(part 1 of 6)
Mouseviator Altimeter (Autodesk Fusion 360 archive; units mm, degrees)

design "Mouseviator Altimeter" references "ULN2003 Stepper Driver v18", "28BYJ-48", "10 turn potentiometer", "Bezel VSI & ALT MS33549B"
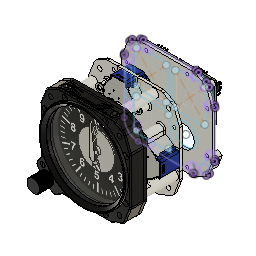
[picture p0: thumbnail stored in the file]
parameter "MagnetDiameter" = 3
parameter "ShaftRotatyToll" = 0.3
parameter "ShaftThickness" = 1
parameter "GluePressFitToll" = 0.1
parameter "squareShaft" = 3.5
parameter "StepperTightness" = 0.3
parameter "DShaftToll" = 0.2
canvas "Canvas1"
canvas "Canvas1" bodies "Faceplate"
external_derived "Front Face" bodies "ALT VSI Bezel", "Seal", "Body1", "Body2", "Top LED Holder"
derived_instance "DerivedInstance1"
derived_instance "DerivedInstance1"
derived_instance "DerivedInstance2"
derived_instance "DerivedInstance3"
derived_instance "DerivedInstance4"
derived_instance "DerivedInstance1"
derived_instance "DerivedInstance2"
extrude "Extrude3" cut of existing geometry blind -0.15
extrude "Extrude4" cut of existing geometry blind -0.15
offset_faces "OffsetFaces1" distance -0.15
extrude "Extrude2" add of existing geometry blind 1.5
extrude "Extrude1" add of existing geometry to an object
sketch "Sketch1" plane through (0, -11.25, 0) normal (0, -1, 0) x axis (1, 0, 0)
  line L1 (-36.3096, -14.7229) -> (-36.3096, -14.4805)
  line L2 (-40.0857, -22.5033) -> (-36.8335, -18.2363)
  line L3 (-18.2363, -36.8335) -> (-22.5033, -40.0857)
  line L4 (-14.4805, -36.3096) -> (-14.7229, -36.3096)
  line L5 (-76.9392, 0) -> (0, 0)
  line L6 (-34.4483, -34.4483) -> (-27.3564, -27.3564)
  line L7 (-40.9575, -25.2062) -> (-40.9575, -24.9738)
  line L8 (-24.9738, -40.9575) -> (-25.2062, -40.9575)
  line L9 (-11.883, -36.8176) -> (-12.0286, -36.8176)
  line L10 (-36.8176, -12.0286) -> (-36.8176, -11.883)
  arc A1 centre (0, 0) radius 39.0906 clockwise from (-36.3096, -14.4805) to (-14.4805, -36.3096)
  arc A2 centre (-39.7627, -16.0038) radius 3.683 clockwise from (-36.3096, -14.7229) to (-36.8335, -18.2363)
  arc A3 centre (0, 0) radius 48.7172 clockwise from (-27.4986, -40.2143) to (-40.2143, -27.4986)
  arc A4 centre (-16.0038, -39.7627) radius 3.683 clockwise from (-18.2363, -36.8335) to (-14.7229, -36.3096)
  circle C1 centre (-30.9023, -30.9023) radius 2.5
  arc A5 centre (-36.6919, -25.09) radius 4.2672 clockwise from (-40.9575, -24.9738) to (-40.0857, -22.5033)
  arc A6 centre (-36.6919, -25.09) radius 4.2672 clockwise from (-40.2143, -27.4986) to (-40.9575, -25.2062)
  arc A7 centre (-25.09, -36.6919) radius 4.2672 clockwise from (-25.2062, -40.9575) to (-27.4986, -40.2143)
  arc A8 centre (-25.09, -36.6919) radius 4.2672 clockwise from (-22.5033, -40.0857) to (-24.9738, -40.9575)
  arc A9 centre (0, 0) radius 38.6878 clockwise from (-11.883, -36.8176) to (-36.8176, -11.883)
  arc A10 centre (0, 0) radius 38.7327 clockwise from (-36.8176, -12.0286) to (-12.0286, -36.8176)
  point P4 (0, 0)
  point P15 (0, 0)
  point P19 (-34.4483, -34.4483)
  point P17 (-30.9023, -30.9023)
  point P20 (-30.9023, -30.9023)
  coincident P4 P15
  horizontal L5
  midpoint A3 P19
  midpoint P17 L6
  coincident P17 P20
  dimension "d3" diameter C1 = 5
extrude "Extrude1" cut sketch "Sketch1" profile of C1 to an object
work_plane "WorkPlane1" AlongDistance 0
sketch "Sketch1" plane through (0, 3.5, 0) normal (0, 1, 0) x axis (1, 0, 0)
  line L1 (-41.4655, 25.2129) -> (-41.4655, 24.9671)
  line L2 (-24.9671, 41.4655) -> (-25.2129, 41.4655)
  line L3 (-25.2129, 41.4655) -> (-28.9018, 41.4655)
  line L4 (21.3665, 41.4655) -> (-24.9671, 41.4655)
  line L5 (-41.4655, 24.9671) -> (-41.4655, -20.5361)
  line L6 (-41.4655, 28.9018) -> (-41.4655, 25.2129)
  curve K1 (21.9088, 41.4365) -> (21.3665, 41.4655)
  curve K2 (-41.4655, -20.5361) -> (-41.4365, -21.0784)
  line L7 (-24.1331, -41.4655) -> (24.1231, -41.4655)
  line L8 (26.5251, -40.8618) -> (33.6166, -37.0564)
  line L9 (-41.1157, -22.3885) -> (-36.4994, -34.1766)
  line L10 (33.6166, 37.0564) -> (23.2139, 41.1177)
  line L11 (41.1157, 22.3885) -> (36.4994, 34.1766)
  line L12 (41.4655, -20.5361) -> (41.4655, 20.5361)
  line L13 (36.4994, -34.1766) -> (41.1157, -22.3885)
  line L14 (-34.1546, -36.8093) -> (-26.5185, -40.8706)
  line L15 (32.6235, -7.6129) -> (25.3452, -5.7982)
  line L16 (-23.1116, -7.251) -> (-17.3893, -5.4467)
  line L17 (2.4638, 0) -> (0, 0)
  line L18 (57.0791, 0) -> (2.4638, 0)
  line L19 (32.6737, 7.3944) -> (25.3452, 5.7982)
  line L20 (-23.1116, 7.251) -> (-17.3893, 5.4467)
  arc A1 centre (-36.3855, -20.5361) radius 5.08 clockwise from (-41.1157, -22.3885) to (-41.4365, -21.0784)
  circle C1 centre (-31.4309, -31.4309) radius 2.159
  circle C2 centre (31.4309, 31.4309) radius 2.159
  circle C3 centre (31.4309, -31.4309) radius 2.159
  arc A2 centre (-28.9018, 28.9018) radius 12.5637 clockwise from (-41.4655, 28.9018) to (-28.9018, 41.4655)
  arc A3 centre (24.1231, -36.3855) radius 5.08 clockwise from (26.5251, -40.8618) to (24.1231, -41.4655)
  circle C4 centre (36.96, -18.76) radius 1.4
  circle C5 centre (18.76, 36.96) radius 1.4
  circle C6 centre (-18.76, -36.96) radius 1.4
  circle C7 centre (-36.96, -18.76) radius 1.4
  circle C8 centre (36.96, 18.76) radius 1.4
  circle C9 centre (18.76, -36.96) radius 1.4
  arc A4 centre (21.3665, 36.3855) radius 5.08 clockwise from (21.9088, 41.4365) to (23.2139, 41.1177)
  arc A5 centre (31.7692, 32.3242) radius 5.08 clockwise from (33.6166, 37.0564) to (36.4994, 34.1766)
  arc A6 centre (36.3855, 20.5361) radius 5.08 clockwise from (41.1157, 22.3885) to (41.4655, 20.5361)
  arc A7 centre (36.3855, -20.5361) radius 5.08 clockwise from (41.4655, -20.5361) to (41.1157, -22.3885)
  arc A8 centre (31.7692, -32.3242) radius 5.08 clockwise from (36.4994, -34.1766) to (33.6166, -37.0564)
  arc A9 centre (-24.1331, -36.3855) radius 5.08 clockwise from (-24.1331, -41.4655) to (-26.5185, -40.8706)
  arc A10 centre (-31.7692, -32.3242) radius 5.08 clockwise from (-34.1546, -36.8093) to (-36.4994, -34.1766)
  circle C10 centre (-0.2224, -0.034) radius 5.25
  arc A11 centre (0, 0) radius 26 clockwise from (26, 0) to (25.3452, -5.7982)
  arc A12 centre (-0.2224, -0.034) radius 18 clockwise from (-17.3893, -5.4467) to (-18.2224, 0)
  arc A13 centre (0, 0) radius 33.5 clockwise from (33.5, 0.0066) to (32.6235, -7.6129)
  arc A14 centre (-0.2224, -0.034) radius 24 clockwise from (-23.1116, -7.251) to (-24.2223, 0.0113)
  arc A15 centre (0, 0) radius 26 clockwise from (25.3452, 5.7982) to (26, 0)
  arc A16 centre (0, 0) radius 33.5 clockwise from (32.6737, 7.3944) to (33.5, 0)
  arc A17 centre (0, 0) radius 18.2224 clockwise from (-18.2224, 0) to (-17.3893, 5.4467)
  arc A18 centre (-0.2224, 0.034) radius 24 clockwise from (-24.2223, -0.0113) to (-23.1116, 7.251)
  arc A19 centre (-4, 0) radius 34 clockwise from (-22.2672, -28.6759) to (-23.5025, -27.8505)
  point P47 (-0.2224, -0.034)
  point P51 (-0.2224, -0.034)
  point P1 (0, 0)
  point P50 (26, 0)
  point P52 (-18.2224, 0)
  point P60 (0, 0)
  point P49 (25.3452, -5.7982)
  point P64 (25.3452, 5.7982)
  point P69 (-18.2224, 0)
  point P53 (-17.3893, -5.4467)
  point P70 (-17.3893, 5.4467)
  point P58 (-23.1116, -7.251)
  point P73 (-23.1116, 7.251)
  point P59 (-24.2223, 0.0113)
  point P72 (-24.2223, -0.0113)
  point P68 (0, 0)
  point P48 (0, 0)
  point P66 (0, 0)
  point P67 (33.5, 0)
  point P54 (0, 0)
  coincident P47 P51
  horizontal P1 P50
  horizontal P1 P52
  coincident P1 P60
  horizontal L17
  parallel L17 L18
  symmetric P49 L18 P64
  symmetric A11 L18 A15
  symmetric P52 L18 P69
  symmetric P53 L18 P70
  symmetric A13 L18 A16
  symmetric P58 L18 P73
  symmetric P59 L18 P72
  symmetric A14 L18 A18
  concentric A11 A13
  coincident P1 P68
  coincident P48 P66
  coincident L18 P67
  coincident P1 P54
  dimension "d7" diameter C10 = 10.5
  dimension "d9" = 6
  dimension "d257" angle L16 L18 = 17.5
  dimension "d258" angle L15 L18 = 14
  dimension "d259" distance A11 A13 = 7.5
  dimension "d260" radius A11 = 26
  dimension "d261" radius A12 = 18
extrude "Extrude1" new body sketch "Sketch1" profile of L1 L2 L3 L4 L5 L6 K1 K2 A1 C1 C2 C3 A2 A3 L7 C4 C5 C6 C7 C8 C9 L8 L9 A4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 along normal blind 3 bodies "Faceplate"
sketch "Sketch2" plane through (0, 6.5, 0) normal (0, 1, 0) x axis (-1, 0, 0)
  line L1 (-25.3452, 5.7982) -> (-32.6235, 7.6129)
  line L2 (-32.6737, -7.3944) -> (-25.3452, -5.7982)
  line L3 (36.4994, 34.1766) -> (41.1157, 22.3885)
  line L4 (26.5185, 40.8706) -> (34.1546, 36.8093)
  line L5 (-24.1231, 41.4655) -> (24.1331, 41.4655)
  line L6 (-33.6166, 37.0564) -> (-26.5251, 40.8618)
  line L7 (-41.1157, 22.3885) -> (-36.4994, 34.1766)
  line L8 (-41.4655, -20.5361) -> (-41.4655, 20.5361)
  line L9 (-36.4994, -34.1766) -> (-41.1157, -22.3885)
  line L10 (-23.2139, -41.1177) -> (-33.6166, -37.0564)
  curve K1 (-21.3665, -41.4655) -> (-21.9088, -41.4365)
  line L11 (28.9018, -41.4655) -> (-21.3665, -41.4655)
  line L12 (41.4655, 20.5361) -> (41.4655, -28.9018)
  curve K2 (41.4365, 21.0784) -> (41.4655, 20.5361)
  line L13 (34.6676, -34.6676) -> (0, 0)
  line L14 (41.4655, 0) -> (0, 0)
  arc A1 centre (0, 0) radius 26 clockwise from (-25.3452, -5.7982) to (-25.3452, 5.7982)
  arc A2 centre (0, 0) radius 33.5 clockwise from (-32.6737, -7.3944) to (-32.6235, 7.6129)
  circle C1 centre (0, 0) radius 5.25
  circle C2 centre (-18.76, 36.96) radius 1.4
  circle C3 centre (-36.96, -18.76) radius 1.4
  circle C4 centre (36.96, 18.76) radius 1.4
  circle C5 centre (18.76, 36.96) radius 1.4
  circle C6 centre (-18.76, -36.96) radius 1.4
  circle C7 centre (-36.96, 18.76) radius 1.4
  circle C8 centre (-31.4309, 31.4309) radius 2.159
  circle C9 centre (-31.4309, -31.4309) radius 2.159
  circle C10 centre (31.4309, 31.4309) radius 2.159
  arc A3 centre (36.3855, 20.5361) radius 5.08 clockwise from (41.1157, 22.3885) to (41.4365, 21.0784)
  arc A4 centre (31.7692, 32.3242) radius 5.08 clockwise from (34.1546, 36.8093) to (36.4994, 34.1766)
  arc A5 centre (24.1331, 36.3855) radius 5.08 clockwise from (24.1331, 41.4655) to (26.5185, 40.8706)
  arc A6 centre (-24.1231, 36.3855) radius 5.08 clockwise from (-26.5251, 40.8618) to (-24.1231, 41.4655)
  arc A7 centre (-31.7692, 32.3242) radius 5.08 clockwise from (-36.4994, 34.1766) to (-33.6166, 37.0564)
  arc A8 centre (-36.3855, 20.5361) radius 5.08 clockwise from (-41.4655, 20.5361) to (-41.1157, 22.3885)
  arc A9 centre (-36.3855, -20.5361) radius 5.08 clockwise from (-41.1157, -22.3885) to (-41.4655, -20.5361)
  arc A10 centre (-31.7692, -32.3242) radius 5.08 clockwise from (-33.6166, -37.0564) to (-36.4994, -34.1766)
  arc A11 centre (-21.3665, -36.3855) radius 5.08 clockwise from (-21.9088, -41.4365) to (-23.2139, -41.1177)
  arc A12 centre (28.9018, -28.9018) radius 12.5637 clockwise from (41.4655, -28.9018) to (28.9018, -41.4655)
  circle C11 centre (0, 0) radius 37
  circle C12 centre (29.7178, -29.7178) radius 12.5
  circle C13 centre (0, 0) radius 10
  point P49 (29.7178, -29.7178)
  point P1 (0, 0)
  point P52 (0, 0)
  point P58 (0, 0)
  point P59 (41.4655, 0)
  point P48 (0, 0)
  point P53 (0, 0)
  point P50 (0, 0)
  point P51 (34.6676, -34.6676)
  coincident P49 L13
  coincident P1 P52
  coincident P52 P58
  coincident L12 P59
  perpendicular L12 L14
  coincident P48 P53
  coincident P50 P53
  dimension "d23" diameter C12 = 25
  dimension "d25" distance P49 P51 = 7
  dimension "d26" diameter C13 = 20
  dimension "d120" diameter C11 = 74
  dimension "d286" angle L13 L14 = 45
extrude "Extrude2" cut sketch "Sketch2" profile of L1 A1 L2 A2 C11 C12 C13 against normal blind 2
work_plane "WorkPlane1" AlongDistance 0
sketch "Wheel Shape" plane through (0, 4.5, 0) normal (0, 1, 0) x axis (1, 0, 0)
  circle C1 centre (0, 0) radius 36.65
  circle C2 centre (-25, 0) radius 1.5
  circle C3 centre (0, 0) radius 10
  circle C4 centre (0, 0) radius 10.35
  circle C5 centre (0, 0) radius 37
  point P1 (0, 0)
  point P2 (0, 0)
  point P3 (-25, 0)
  coincident P1 P2
  horizontal P1 P3
  dimension "d17" distance C1 C5 = 0.35
  dimension "d19" diameter C2 = 3 (= "MagnetDiameter")
  dimension "d20" distance P1 P3 = 25
  dimension "d27" = 0.35 (= "d17")
extrude "Extrude1" new body sketch "Wheel Shape" profile of C1 C2 C4 along normal blind 1 bodies "Wheel"
work_plane "WorkPlane1" AlongDistance 0
work_plane "WorkPlane2" AlongDistance 30
sketch "Motor Position and Extrude" plane through (0, 36.5, 0) normal (0, 1, 0) x axis (1, 0, 0)
  line L1 (-41.4655, 25.2129) -> (-41.4655, 24.9671)
  line L2 (-24.9671, 41.4655) -> (-25.2129, 41.4655)
  line L3 (-25.2129, 41.4655) -> (-28.9018, 41.4655)
  line L4 (21.3665, 41.4655) -> (-24.9671, 41.4655)
  line L5 (-41.4655, 24.9671) -> (-41.4655, -20.5361)
  line L6 (-41.4655, 28.9018) -> (-41.4655, 25.2129)
  curve K1 (21.9088, 41.4365) -> (21.3665, 41.4655)
  curve K2 (-41.4655, -20.5361) -> (-41.4365, -21.0784)
  line L7 (-24.1331, -41.4655) -> (24.1231, -41.4655)
  line L8 (26.5251, -40.8618) -> (33.6166, -37.0564)
  line L9 (-41.1157, -22.3885) -> (-36.4994, -34.1766)
  line L10 (33.6166, 37.0564) -> (23.2139, 41.1177)
  line L11 (41.1157, 22.3885) -> (36.4994, 34.1766)
  line L12 (41.4655, -20.5361) -> (41.4655, 20.5361)
  line L13 (36.4994, -34.1766) -> (41.1157, -22.3885)
  line L14 (-34.1546, -36.8093) -> (-26.5185, -40.8706)
  line L15 (-5.9161, -17) -> (0, 0)
  line L16 (17.2921, 4.9983) -> (0, 0)
  line L17 (-5.9161, 0) -> (-5.9161, -17)
  line L18 (0, 0) -> (-5.9161, 0)
  line L19 (17.2921, 0) -> (0, 0)
  line L20 (17.2921, 0) -> (17.2921, 4.9983)
  line L21 (0, 0) -> (17.2921, 0)
  line L22 (17.2921, 0) -> (0, 0)
  line L23 (0, -31.4521) -> (0, 0)
  circle C1 centre (-30.9023, 30.9023) radius 2.5
  arc A1 centre (-36.3855, -20.5361) radius 5.08 clockwise from (-41.1157, -22.3885) to (-41.4365, -21.0784)
  circle C2 centre (-31.4309, -31.4309) radius 2.159
  circle C3 centre (31.4309, 31.4309) radius 2.159
  circle C4 centre (31.4309, -31.4309) radius 2.159
  arc A2 centre (-28.9018, 28.9018) radius 12.5637 clockwise from (-41.4655, 28.9018) to (-28.9018, 41.4655)
  arc A3 centre (24.1231, -36.3855) radius 5.08 clockwise from (26.5251, -40.8618) to (24.1231, -41.4655)
  circle C5 centre (36.96, -18.76) radius 1
  circle C6 centre (18.76, 36.96) radius 1
  circle C7 centre (-18.76, -36.96) radius 1
  circle C8 centre (-36.96, -18.76) radius 1
  circle C9 centre (36.96, 18.76) radius 1
  circle C10 centre (18.76, -36.96) radius 1
  arc A4 centre (21.3665, 36.3855) radius 5.08 clockwise from (21.9088, 41.4365) to (23.2139, 41.1177)
  arc A5 centre (31.7692, 32.3242) radius 5.08 clockwise from (33.6166, 37.0564) to (36.4994, 34.1766)
  arc A6 centre (36.3855, 20.5361) radius 5.08 clockwise from (41.1157, 22.3885) to (41.4655, 20.5361)
  arc A7 centre (36.3855, -20.5361) radius 5.08 clockwise from (41.4655, -20.5361) to (41.1157, -22.3885)
  arc A8 centre (31.7692, -32.3242) radius 5.08 clockwise from (36.4994, -34.1766) to (33.6166, -37.0564)
  arc A9 centre (-24.1331, -36.3855) radius 5.08 clockwise from (-24.1331, -41.4655) to (-26.5185, -40.8706)
  arc A10 centre (-31.7692, -32.3242) radius 5.08 clockwise from (-34.1546, -36.8093) to (-36.4994, -34.1766)
  circle C11 centre (0, 0) radius 5
  circle C12 centre (-5.9161, -17) radius 2
  circle C13 centre (17.2921, 4.9983) radius 2
  circle C14 centre (-30.9023, 30.9023) radius 5.5
  point P48 (0, 0)
  point P51 (0, 0)
  point P49 (-5.9161, -17)
  point P52 (-5.9161, -17)
  point P50 (17.2921, 4.9983)
  point P53 (17.2921, 4.9983)
  point P54 (0, 0)
  point P55 (-5.9161, -17)
  point P57 (17.2921, 4.9983)
  point P59 (0, 0)
  point P60 (0, 0)
  coincident P48 P51
  coincident P49 P52
  coincident P50 P53
  coincident P48 P54
  coincident P49 P55
  vertical L17
  horizontal L18
  coincident P50 P57
  perpendicular L19 L20
  coincident P48 P59
  horizontal L19
  coincident P48 P60
  perpendicular L22 L23
  concentric C1 C14
  dimension "d43" diameter C13 = 4
  dimension "d44" diameter C12 = 4
  dimension "d300" distance P51 P52 = 18
  dimension "d302" distance P51 P53 = 18
  dimension "d306" diameter C14 = 11
extrude "Extrude1" new body sketch "Motor Position and Extrude" profile of L1 L2 L3 L4 L5 L6 K1 K2 A1 C2 C3 C4 A2 A3 L7 C5 C6 C7 C8 C9 C10 L8 L9 A4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 along normal blind 2.5
copy_paste "CutPaste1"
component_insert "Component Insert1"
joint "Assemble1" alignAngle -90 alignOffsetX 0 alignOffsetY 0 alignOffsetZ -10
component_insert "Component Insert2"
joint "Assemble2" alignAngle 0 alignOffsetX 0 alignOffsetY 0 alignOffsetZ -18
component_insert "Component Insert3"
joint "Assemble3" alignAngle -135 alignOffsetX 0 alignOffsetY 0 alignOffsetZ -0.25
sketch "Motor Spacers" plane through (0, 39, 0) normal (0, 1, 0) x axis (-1, 0, 0)
  line L1 (36.4994, 34.1766) -> (41.1157, 22.3885)
  line L2 (26.5185, 40.8706) -> (34.1546, 36.8093)
  line L3 (-24.1231, 41.4655) -> (24.1331, 41.4655)
  line L4 (-33.6166, 37.0564) -> (-26.5251, 40.8618)
  line L5 (-41.1157, 22.3885) -> (-36.4994, 34.1766)
  line L6 (-41.4655, -20.5361) -> (-41.4655, 20.5361)
  line L7 (-36.4994, -34.1766) -> (-41.1157, -22.3885)
  line L8 (-23.2139, -41.1177) -> (-33.6166, -37.0564)
  curve K1 (-21.3665, -41.4655) -> (-21.9088, -41.4365)
  line L9 (28.9018, -41.4655) -> (-21.3665, -41.4655)
  line L10 (41.4655, 20.5361) -> (41.4655, -28.9018)
  curve K2 (41.4365, 21.0784) -> (41.4655, 20.5361)
  line L11 (-28.1171, -18.8029) -> (-28.1171, -22.4983)
  line L12 (-21.1171, -22.4983) -> (-21.1171, -18.8029)
  line L13 (-21.1171, 8.8064) -> (-21.1171, 12.5017)
  line L14 (-28.1171, 12.5017) -> (-28.1171, 8.8064)
  line L15 (-2.2528, -17.5616) -> (-4.7199, -20.0288)
  line L16 (-9.6697, -15.0791) -> (-7.2025, -12.6119)
  line L17 (12.6119, 7.2025) -> (15.0791, 9.6697)
  line L18 (20.0288, 4.7199) -> (17.5616, 2.2528)
  line L19 (19.7207, 20.825) -> (23.4161, 20.825)
  line L20 (23.4161, 27.825) -> (19.7207, 27.825)
  line L21 (-7.8886, 27.825) -> (-11.5839, 27.825)
  line L22 (-11.5839, 20.825) -> (-7.8886, 20.825)
  circle C1 centre (36.96, 18.76) radius 1
  circle C2 centre (18.76, 36.96) radius 1
  circle C3 centre (-36.96, -18.76) radius 1
  circle C4 centre (-31.4309, -31.4309) radius 2.159
  circle C5 centre (31.4309, 31.4309) radius 2.159
  arc A1 centre (36.3855, 20.5361) radius 5.08 clockwise from (41.1157, 22.3885) to (41.4365, 21.0784)
  arc A2 centre (31.7692, 32.3242) radius 5.08 clockwise from (34.1546, 36.8093) to (36.4994, 34.1766)
  arc A3 centre (24.1331, 36.3855) radius 5.08 clockwise from (24.1331, 41.4655) to (26.5185, 40.8706)
  arc A4 centre (-24.1231, 36.3855) radius 5.08 clockwise from (-26.5251, 40.8618) to (-24.1231, 41.4655)
  arc A5 centre (-31.7692, 32.3242) radius 5.08 clockwise from (-36.4994, 34.1766) to (-33.6166, 37.0564)
  arc A6 centre (-36.3855, 20.5361) radius 5.08 clockwise from (-41.4655, 20.5361) to (-41.1157, 22.3885)
  arc A7 centre (-36.3855, -20.5361) radius 5.08 clockwise from (-41.1157, -22.3885) to (-41.4655, -20.5361)
  arc A8 centre (-31.7692, -32.3242) radius 5.08 clockwise from (-33.6166, -37.0564) to (-36.4994, -34.1766)
  arc A9 centre (-21.3665, -36.3855) radius 5.08 clockwise from (-21.9088, -41.4365) to (-23.2139, -41.1177)
  arc A10 centre (28.9018, -28.9018) radius 12.5637 clockwise from (41.4655, -28.9018) to (28.9018, -41.4655)
  arc A11 centre (-24.6171, -4.9983) radius 14.2414 clockwise from (-21.1171, -18.8029) to (-28.1171, -18.8029)
  arc A12 centre (-24.6171, -22.4983) radius 3.5 clockwise from (-21.1171, -22.4983) to (-28.1171, -22.4983)
  circle C6 centre (-24.6171, -22.4983) radius 2
  arc A13 centre (-24.6171, -4.9983) radius 14.2414 clockwise from (-28.1171, 8.8064) to (-21.1171, 8.8064)
  arc A14 centre (-24.6171, 12.5017) radius 3.5 clockwise from (-28.1171, 12.5017) to (-21.1171, 12.5017)
  circle C7 centre (-24.6171, 12.5017) radius 2
  arc A15 centre (5.1796, -5.1796) radius 14.4414 clockwise from (-2.2528, -17.5616) to (-7.2025, -12.6119)
  arc A16 centre (-7.1948, -17.5539) radius 3.5 clockwise from (-4.7199, -20.0288) to (-9.6697, -15.0791)
  circle C8 centre (-7.1948, -17.5539) radius 2
  arc A17 centre (5.1796, -5.1796) radius 14.4414 clockwise from (12.6119, 7.2025) to (17.5616, 2.2528)
  arc A18 centre (17.5539, 7.1948) radius 3.5 clockwise from (15.0791, 9.6697) to (20.0288, 4.7199)
  circle C9 centre (17.5539, 7.1948) radius 2
  arc A19 centre (5.9161, 24.325) radius 14.2414 clockwise from (19.7207, 27.825) to (19.7207, 20.825)
  arc A20 centre (23.4161, 24.325) radius 3.5 clockwise from (23.4161, 27.825) to (23.4161, 20.825)
  circle C10 centre (23.4161, 24.325) radius 2
  arc A21 centre (5.9161, 24.325) radius 14.2414 clockwise from (-7.8886, 20.825) to (-7.8886, 27.825)
  arc A22 centre (-11.5839, 24.325) radius 3.5 clockwise from (-11.5839, 20.825) to (-11.5839, 27.825)
  circle C11 centre (-11.5839, 24.325) radius 2
  circle C12 centre (-24.6171, -22.4983) radius 1.4
  circle C13 centre (-24.6171, 12.5017) radius 1.4
  circle C14 centre (-7.1948, -17.5539) radius 1.4
  circle C15 centre (17.5539, 7.1948) radius 1.4
  circle C16 centre (23.4161, 24.325) radius 1.4
  circle C17 centre (-11.5839, 24.325) radius 1.4
  circle C18 centre (-18.76, -36.96) radius 1
  circle C19 centre (0, 0) radius 5
  circle C20 centre (-31.4309, 31.4309) radius 2.159
  circle C21 centre (-36.96, 18.76) radius 1
  circle C22 centre (-18.76, 36.96) radius 1
  circle C23 centre (30.9023, -30.9023) radius 5.5
  point P68 (23.4161, 24.325)
  point P79 (23.4161, 24.325)
  concentric A12 C12
  concentric A14 C13
  concentric A16 C14
  concentric A18 C15
  coincident P68 P79
  concentric A22 C17
  equal C16 C17
  equal C15 C16
  equal C14 C15
  equal C12 C14
  equal C12 C13
  dimension "d76" diameter C13 = 2.8
extrude "Extrude7" cut sketch "Motor Spacers" profile of C14 C15 to an object
extrude "Extrude8" add sketch "Motor Spacers" profile of L19 L20 A20 L21 L22 A22 C16 C17 to an object
extrude "Extrude9" add sketch "Motor Spacers" profile of L11 A11 L12 A12 L13 A13 L14 A14 C12 C13 to an object
base_feature "Base Feature1"
sketch "Sketch1" plane through (0, 0, 0) normal (0, 0, 1) x axis (1, 0, 0)
  circle C1 centre (0, 0) radius 6.25
  point P1 (0, 0)
  point P2 (0, 0)
  coincident P1 P2
  dimension "d23_1" diameter C1 = 12.5
extrude "Extrude1" new body sketch "Sketch1" along a picked direction blind 12.5 named "d24_1" from offset 1
sketch "Sketch2" plane through (0, 0, 1) normal (0, 0, -1) x axis (1, 0, 0)
  circle C1 centre (0, 0) radius 6.25
  circle C2 centre (0, 0) radius 3.075
  point P1 (0, 0)
  point P3 (0, 0)
  coincident P1 P3
  dimension "d26_1" diameter C2 = 6.15
sketch "Sketch3" plane through (0, 0, 13.5) normal (0, 0, 1) x axis (-1, 0, 0)
  circle C1 centre (0, 0) radius 6.25
  circle C2 centre (0, 0) radius 6.25
  circle C3 centre (0, 0) radius 5.5
  point P1 (0, 0)
  point P3 (0, 0)
  coincident P1 P3
  dimension "d29_1" = -0.75
extrude "Extrude3" add sketch "Sketch3" along normal blind 0.5 named "d30_1"
extrude "Extrude4" cut of existing geometry to an object
chamfer "Chamfer1" distance 0.5
coil_primitive "CoilPrimitive1" Diameter 12.5 SectionSize 0.5 TaperAngle 0 Height 13.5
mirror "Mirror1"
circular_pattern "C-Pattern1" TotalAngle 360
sketch "Sketch13" plane through (0, 0, 1) normal (0, 0, -1) x axis (1, 0, 0)
  curve K1 (-4.3957, 4.3957) -> (-3.4415, 4.9149)
  curve K2 (5.9088, 1.0419) -> (6.2165, 0)
  curve K3 (-6.2165, 0) -> (-5.9088, 1.0419)
  curve K4 (3.4415, 4.9149) -> (4.3957, 4.3957)
  curve K5 (-4.3957, -4.3957) -> (-4.9149, -3.4415)
  curve K6 (-1.0419, 5.9088) -> (0, 6.2165)
  curve K7 (0, -6.2165) -> (-1.0419, -5.9088)
  curve K8 (-4.9149, 3.4415) -> (-4.3957, 4.3957)
  curve K9 (4.3957, -4.3957) -> (3.4415, -4.9149)
  curve K10 (-5.9088, -1.0419) -> (-6.2165, 0)
  curve K11 (6.2165, 0) -> (5.9088, -1.0419)
  curve K12 (-3.4415, -4.9149) -> (-4.3957, -4.3957)
  curve K13 (4.3957, 4.3957) -> (4.9149, 3.4415)
  curve K14 (1.0419, -5.9088) -> (0, -6.2165)
  curve K15 (0, 6.2165) -> (1.0419, 5.9088)
  curve K16 (4.9149, -3.4415) -> (4.3957, -4.3957)
  line L1 (-1.575, 0) -> (-3.075, 0)
  line L2 (-1.575, -2.641) -> (-1.575, 2.641)
  curve K17 (-3.4415, 4.9149) -> (-2.4875, 5.7337)
  curve K18 (-5.7337, 2.4875) -> (-4.9149, 3.4415)
  curve K19 (-5.9088, 1.0419) -> (-5.8132, 2.2954)
  curve K20 (-5.8132, -2.2954) -> (-5.9088, -1.0419)
  curve K21 (-4.9149, -3.4415) -> (-5.7337, -2.4875)
  curve K22 (-2.4875, -5.7337) -> (-3.4415, -4.9149)
  curve K23 (-1.0419, -5.9088) -> (-2.2954, -5.8132)
  curve K24 (2.2954, -5.8132) -> (1.0419, -5.9088)
  curve K25 (3.4415, -4.9149) -> (2.4875, -5.7337)
  curve K26 (5.7337, -2.4875) -> (4.9149, -3.4415)
  curve K27 (5.9088, -1.0419) -> (5.8132, -2.2954)
  curve K28 (5.8132, 2.2954) -> (5.9088, 1.0419)
  curve K29 (4.9149, 3.4415) -> (5.7337, 2.4875)
  curve K30 (2.4875, 5.7337) -> (3.4415, 4.9149)
  curve K31 (1.0419, 5.9088) -> (2.2954, 5.8132)
  curve K32 (-2.2954, 5.8132) -> (-1.0419, 5.9088)
  arc A1 centre (0, 0) radius 6.25 clockwise from (-5.8132, 2.2954) to (-5.7337, 2.4875)
  arc A2 centre (0, 0) radius 6.25 clockwise from (-5.7337, -2.4875) to (-5.8132, -2.2954)
  arc A3 centre (0, 0) radius 6.25 clockwise from (-2.2954, -5.8132) to (-2.4875, -5.7337)
  arc A4 centre (0, 0) radius 6.25 clockwise from (2.4875, -5.7337) to (2.2954, -5.8132)
  arc A5 centre (0, 0) radius 6.25 clockwise from (5.8132, -2.2954) to (5.7337, -2.4875)
  arc A6 centre (0, 0) radius 6.25 clockwise from (5.7337, 2.4875) to (5.8132, 2.2954)
  arc A7 centre (0, 0) radius 6.25 clockwise from (2.2954, 5.8132) to (2.4875, 5.7337)
  arc A8 centre (0, 0) radius 6.25 clockwise from (-2.4875, 5.7337) to (-2.2954, 5.8132)
  point P27 (-3.075, 0)
  point P28 (-1.575, 0)
  horizontal L1
  perpendicular L1 L2
  dimension "d46_1" distance P27 P28 = 1.5
work_plane "WorkPlane1" AlongDistance 1
canvas "Canvas1" bodies "10K Needle"
sketch "Pointer" plane through (0, 2.5, 0) normal (0, -1, 0) x axis (1, 0, 0)
  line L1 (-3.7809, 16.061) -> (-2.1183, 19.2337)
  line L2 (0, 0) -> (-2.1183, 19.2337)
  line L3 (0.195, 16.4988) -> (-2.1183, 19.2337)
  line L4 (1.8063, -16.4008) -> (0, 0)
  line L5 (-2.2791, -16.3418) -> (-1.0026, -7.6255)
  line L6 (5.7809, -15.4542) -> (2.6381, -7.2245)
  circle C1 centre (0, 0) radius 16.5
  circle C2 centre (0, 0) radius 5
  circle C3 centre (0, 0) radius 4
  arc A1 centre (-0.1807, -0.3465) radius 7.3252 clockwise from (0.8371, -7.6007) to (-1.0026, -7.6255)
  arc A2 centre (0.2518, -0.2989) radius 7.3252 clockwise from (2.6381, -7.2245) to (0.8371, -7.6007)
  point P6 (-3.7809, 16.061)
  point P7 (-1.8063, 16.4008)
  point P5 (-2.1183, 19.2337)
  point P8 (-2.1183, 19.2337)
  point P9 (0.195, 16.4988)
  point P4 (0, 0)
  point P10 (0, 0)
  point P11 (1.8063, -16.4008)
  point P1 (0, 0)
  point P16 (0, 0)
  point P15 (0.8371, -7.6007)
  point P12 (-1.0026, -7.6255)
  point P17 (2.6381, -7.2245)
  point P13 (-2.2791, -16.3418)
  point P18 (5.7809, -15.4542)
  point P20 (0.8371, -7.6007)
  point P2 (0, 0)
  point P3 (0, 0)
  coincident C1 P6
  coincident C1 P7
  coincident L2 P7
  symmetric P5 L2 P8
  symmetric P6 L2 P9
  coincident P4 P10
  coincident C1 P11
  parallel L2 L4
  coincident P1 P16
  collinear L2 L4
  coincident L4 P15
  symmetric L4 P12 P17
  symmetric L4 P13 P18
  symmetric L4 P15 P20
  symmetric L4 A1 A2
  coincident C1 P13
  coincident P2 P3
  dimension "d87" distance C2 C3 = 1 (= "ShaftThickness")
  dimension "d156" diameter C1 = 33
  dimension "d157" distance P6 L2 = 2
  dimension "d158" distance P5 P7 = 2.85
  dimension "d310" diameter C2 = 10
extrude "Extrude1" new body sketch "Pointer" profile of C1 C2 C3 L1 L3 L5 A1 L6 A2 along normal blind 0.5 and against normal blind 0.5 bodies "10K Needle"
extrude "Extrude2" add sketch "Pointer" profile of C2 C3 to an object
work_plane "WorkPlane2" AlongDistance 1
sketch "Sketch1" plane through (0, 1, 0) normal (0, -1, 0) x axis (1, 0, 0)
  line L1 (1.2743, 26.8607) -> (-1.0417, 26.8607)
  line L2 (1.2743, 5.5738) -> (1.2743, 26.8607)
  line L3 (-1.0417, 5.5738) -> (1.2743, 5.5738)
  line L4 (-1.0417, 26.8607) -> (-1.0417, 5.5738)
  line L5 (-22.1181, 16.3229) -> (0, 0)
  line L6 (-16.2012, 11.5652) -> (-16.0144, 11.8184)
  line L7 (-12.2851, 5.9884) -> (-16.2012, 11.5652)
  line L8 (-10.3599, 6.4055) -> (-12.2851, 5.9884)
  line L9 (-0.4309, -2.2617) -> (-10.3599, 6.4055)
  line L10 (4.2996, -4.574) -> (-0.4309, -2.2617)
  line L11 (6.6381, -4.8988) -> (0, 0)
  line L12 (-15.8275, 12.0716) -> (-16.0144, 11.8184)
  line L13 (-9.344, 9.9736) -> (-15.8275, 12.0716)
  line L14 (-9.1751, 8.011) -> (-9.344, 9.9736)
  line L15 (2.0342, 1.0786) -> (-9.1751, 8.011)
  line L16 (5.6383, -2.76) -> (2.0342, 1.0786)
  circle C1 centre (0, 0) radius 4
  circle C2 centre (0, 0) radius 3.7
  circle C3 centre (0, 0) radius 5.7176
  circle C4 centre (0, 0) radius 2.7
  circle C5 centre (6.6381, -4.8988) radius 2.361
  point P8 (1.2743, 5.5738)
  point P5 (0, 0)
  point P10 (0, 0)
  point P12 (-16.0144, 11.8184)
  point P2 (0, 0)
  point P19 (0, 0)
  point P18 (6.6381, -4.8988)
  point P20 (6.6381, -4.8988)
  point P17 (4.2996, -4.574)
  point P21 (-16.0144, 11.8184)
  point P13 (-16.2012, 11.5652)
  point P22 (-15.8275, 12.0716)
  point P14 (-12.2851, 5.9884)
  point P23 (-9.344, 9.9736)
  point P15 (-10.3599, 6.4055)
  point P24 (-9.1751, 8.011)
  point P16 (-0.4309, -2.2617)
  point P25 (2.0342, 1.0786)
  point P26 (5.6383, -2.76)
  concentric C1 C3
  concentric C1 C4
  horizontal L1
  vertical L2
  horizontal L3
  vertical L4
  coincident C3 P8
  coincident P5 P10
  coincident L5 P12
  perpendicular L5 L6
  coincident P2 P19
  coincident P18 P20
  collinear L5 L11
  coincident P17 C5
  symmetric L5 P12 P21
  symmetric L5 P13 P22
  symmetric L5 P14 P23
  symmetric L5 P15 P24
  symmetric L5 P16 P25
  symmetric L5 P17 P26
  dimension "d94" distance C2 C4 = 1 (= "ShaftThickness")
  dimension "d159" distance P19 P20 = 8.25
extrude "Extrude1" new body sketch "Sketch1" profile of C2 C4 L6 L7 L8 L9 L10 C5 L12 L13 L14 L15 L16 along normal blind 1 bodies "1K Needle"
extrude "Extrude2" add sketch "Sketch1" profile of C2 C4 L9 L10 L15 L16 to an object offset 0.25 (= "1.5 mm - 1.25 mm")
work_plane "WorkPlane3" AlongDistance 1
sketch "Sketch1" plane through (0.0945, -1, 10.5185) normal (0, -1, 0) x axis (1, 0, 0)
  line L1 (0.3984, -35.0927) -> (2.132, -5.5266)
  line L2 (-0.0945, -35.0927) -> (-0.0945, -3.3001)
  line L3 (0.3984, -35.0927) -> (-0.0945, -35.0927)
  line L4 (-0.5874, -35.0927) -> (-0.0945, -35.0927)
  line L5 (-0.5874, -35.0927) -> (-2.321, -5.5266)
  circle C1 centre (-0.0945, -10.5185) radius 2.7
  circle C2 centre (-0.0945, -10.5185) radius 2.4
  arc A1 centre (-0.0945, -5.5266) radius 2.2265 clockwise from (-0.0945, -3.3001) to (2.132, -5.5266)
  arc A2 centre (-0.0945, -5.5266) radius 2.2265 clockwise from (-2.321, -5.5266) to (-0.0945, -3.3001)
  point P4 (-0.0945, -5.5266)
  point P5 (2.132, -5.5266)
  point P11 (-2.321, -5.5266)
  point P7 (0.3984, -35.0927)
  point P10 (-0.5874, -35.0927)
  point P8 (-0.0945, -35.0927)
  point P9 (-0.0945, -35.0927)
  point P3 (-0.0945, -10.5185)
  point P13 (-0.0945, -10.5185)
  point P14 (-0.0945, -10.5185)
  point P12 (-0.0945, -5.5266)
  perpendicular L2 L3
  coincident P4 L2
  symmetric P5 L2 P11
  symmetric A1 L2 A2
  symmetric P7 L2 P10
  symmetric P8 L2 P9
  coincident P3 P13
  vertical L2
  coincident L2 P14
  coincident P3 P14
  horizontal P11 P12
  dimension "d378" distance C1 C2 = 0.3 (= "ShaftRotatyToll")
extrude "Extrude1" new body sketch "Sketch1" profile of C2 A1 L1 L3 L4 L5 A2 along normal blind 1 bodies "100ft Needle"
extrude "Extrude2" add sketch "Sketch1" profile of C2 to an object
copy_paste "CutPaste1"
copy_paste "CutPaste2"
copy_paste "CutPaste3"
joint "Assemble1" alignAngle 0 alignOffsetX 0 alignOffsetY 0 alignOffsetZ 0
extrude "Extrude3" cut sketch "Sketch2" profile of L11 A12 L12 C11 C12 to an object
sketch "Wheel Gear" plane through (0, 5.5, 0) normal (0, 1, 0) x axis (-1, 0, 0)
  line L1 (34.8119, 3.6234) -> (34.5455, 3.7079)
  line L2 (34.0217, 3.8564) -> (33.7792, 3.9169)
  line L3 (32.7158, 4.1291) -> (32.6931, 4.1478)
  line L4 (31.9837, 7.9424) -> (31.9982, 7.968)
  line L5 (32.2881, 7.1111) -> (32.2344, 7.1181)
  line L6 (33.5616, 5.4767) -> (33.7783, 5.6013)
  line L7 (32.5775, 4.9459) -> (32.5801, 4.9574)
  line L8 (34.2778, 3.7868) -> (34.0217, 3.8564)
  line L9 (33.3302, 4.0143) -> (33.1232, 4.0524)
  line L10 (32.0748, 7.5439) -> (32.0147, 7.7955)
  line L11 (32.1643, 7.1564) -> (32.1331, 7.2919)
  line L12 (34.5455, 3.7079) -> (34.2778, 3.7868)
  line L13 (32.5974, 4.8083) -> (32.5775, 4.9459)
  line L14 (32.0147, 7.7955) -> (31.9821, 7.9307)
  line L15 (33.1232, 4.0524) -> (32.8065, 4.1016)
  line L16 (32.5801, 4.9574) -> (32.5969, 4.9816)
  line L17 (32.6874, 4.1581) -> (32.6689, 4.2959)
  line L18 (32.0728, 8.0264) -> (32.3504, 8.1868)
  line L19 (31.9821, 7.9307) -> (31.9837, 7.9424)
  line L20 (32.8176, 7.0725) -> (32.608, 7.0913)
  line L21 (34.3291, 6.82) -> (34.056, 6.8796)
  line L22 (33.7822, 6.9334) -> (33.5207, 6.9791)
  line L23 (33.5478, 3.9696) -> (33.3302, 4.0143)
  line L24 (32.634, 4.5523) -> (32.5974, 4.8083)
  line L25 (31.9982, 7.968) -> (32.0279, 7.9963)
  line L26 (34.6386, 2.7029) -> (34.885, 2.835)
  line L27 (32.0279, 7.9963) -> (32.0728, 8.0264)
  line L28 (32.6689, 4.2959) -> (32.634, 4.5523)
  line L29 (32.8065, 4.1016) -> (32.7537, 4.1135)
  line L30 (33.7792, 3.9169) -> (33.5478, 3.9696)
  line L31 (32.7537, 4.1135) -> (32.7158, 4.1291)
  line L32
  line L33 (-27.8444, 18.3918) -> (-28.0466, 18.45)
  line L34 (-27.3291, 18.4073) -> (-27.4071, 18.2922)
  line L35 (-27.4071, 18.2922) -> (-27.4168, 18.2855)
  line L36 (-26.9576, 18.9484) -> (-27.0367, 18.8341)
  line L37 (-27.4664, 19.6675) -> (-27.3357, 19.4878)
  line L38 (-27.2084, 19.3202) -> (-27.0075, 19.0704)
  line L39 (-29.2711, 18.7174) -> (-29.5473, 18.7606)
  line L40 (-28.2614, 18.507) -> (-28.4919, 18.563)
  line L41 (-27.5389, 18.2947) -> (-27.8444, 18.3918)
  line L42 (-28.736, 18.6169) -> (-28.9963, 18.6687)
  line L43 (-27.8827, 20.2944) -> (-27.7404, 20.0703)
  line L44 (-27.4168, 18.2855) -> (-27.4455, 18.2789)
  line L45 (-28.4919, 18.563) -> (-28.736, 18.6169)
  line L46 (-26.9591, 18.989) -> (-26.9548, 18.9599)
  line L47 (-27.3357, 19.4878) -> (-27.2084, 19.3202)
  line L48 (-29.6363, 17.6351) -> (-29.4739, 17.4252)
  line L49 (-28.0466, 18.45) -> (-28.2614, 18.507)
  line L50 (-27.1837, 18.6212) -> (-27.3291, 18.4073)
  line L51 (-27.6019, 19.8622) -> (-27.4664, 19.6675)
  line L52 (-29.9641, 18.0873) -> (-29.8024, 17.8593)
  line L53 (-26.9765, 19.0261) -> (-26.9591, 18.989)
  line L54 (-27.4863, 18.2818) -> (-27.5389, 18.2947)
  line L55 (-27.0367, 18.8341) -> (-27.1837, 18.6212)
  line L56 (-27.7404, 20.0703) -> (-27.6019, 19.8622)
  line L57 (-28.1674, 20.7749) -> (-28.0274, 20.5329)
  line L58 (-29.8024, 17.8593) -> (-29.6363, 17.6351)
  line L59 (-28.9963, 18.6687) -> (-29.2711, 18.7174)
  line L60 (-27.0075, 19.0704) -> (-26.9765, 19.0261)
  line L61 (-25.5141, 20.8504) -> (-25.6024, 20.743)
  line L62 (-25.5346, 22.1178) -> (-25.421, 21.9269)
  line L63 (-25.7702, 22.5443) -> (-25.6515, 22.3243)
  line L64 (-25.7334, 20.7576) -> (-26.0286, 20.8825)
  line L65 (-25.1836, 21.2484) -> (-25.3496, 21.05)
  line L66 (-25.8913, 22.7805) -> (-25.7702, 22.5443)
  line L67 (-26.2246, 20.9591) -> (-26.4332, 21.0356)
  line L68 (-25.6024, 20.743) -> (-25.6127, 20.7372)
  line L69 (-25.3097, 21.7483) -> (-25.1327, 21.481)
  line L70 (-26.6576, 21.1127) -> (-26.8957, 21.1889)
  line L71 (-27.4192, 21.3384) -> (-27.6902, 21.4068)
  line L72 (-25.3333, 23.7773) -> (-25.5969, 23.8704)
  line L73 (-25.6419, 20.7333) -> (-25.6822, 20.74)
  line L74 (-25.421, 21.9269) -> (-25.3097, 21.7483)
  line L75 (-26.0133, 23.0314) -> (-25.8913, 22.7805)
  line L76 (-25.1327, 21.481) -> (-25.1059, 21.434)
  line L77 (-26.8957, 21.1889) -> (-27.1501, 21.2645)
  line L78 (-26.0286, 20.8825) -> (-26.2246, 20.9591)
  line L79 (-26.1304, 23.2853) -> (-26.0133, 23.0314)
  line L80 (-23.6591, 23.0212) -> (-23.7083, 23.0435)
  line L81 (-23.0168, 23.5793) -> (-23.1156, 23.4814)
  line L82 (-25.6515, 22.3243) -> (-25.5346, 22.1178)
  line L83 (-23.7083, 23.0435) -> (-23.9908, 23.195)
  line L84 (-25.0942, 21.3549) -> (-25.1836, 21.2484)
  line L85 (-25.092, 21.3955) -> (-25.0904, 21.3661)
  line L86 (-25.0722, 23.6789) -> (-25.3333, 23.7773)
  line L87 (-25.6822, 20.74) -> (-25.7334, 20.7576)
  line L88 (-25.3496, 21.05) -> (-25.5141, 20.8504)
  line L89 (-26.4332, 21.0356) -> (-26.6576, 21.1127)
  line L90 (-25.1059, 21.434) -> (-25.092, 21.3955)
  line L91 (-27.1501, 21.2645) -> (-27.4192, 21.3384)
  line L92 (-27.4455, 18.2789) -> (-27.4863, 18.2818)
  line L93 (-26.9548, 18.9599) -> (-26.9576, 18.9484)
  line L94 (-25.0904, 21.3661) -> (-25.0942, 21.3549)
  line L95 (-28.0274, 20.5329) -> (-27.8827, 20.2944)
  line L96 (-25.6127, 20.7372) -> (-25.6419, 20.7333)
  line L97 (-23.2894, 24.1789) -> (-23.195, 23.9908)
  line L98 (-23.7773, 25.3333) -> (-23.6789, 25.0722)
  line L99 (-23.6789, 25.0722) -> (-23.5801, 24.8259)
  line L100 (-23.9908, 23.195) -> (-24.1789, 23.2894)
  line L101 (-23.59, 23.012) -> (-23.6194, 23.0108)
  line L102 (-23.012, 23.59) -> (-23.0168, 23.5793)
  line L103 (-23.6194, 23.0108) -> (-23.6591, 23.0212)
  line L104 (-24.8259, 23.5801) -> (-25.0722, 23.6789)
  line L105 (-23.0108, 23.6194) -> (-23.012, 23.59)
  line L106 (-20.7372, 25.6127) -> (-20.743, 25.6024)
  line L107 (-21.3661, 25.0904) -> (-21.3955, 25.092)
  line L108 (-21.7483, 25.3097) -> (-21.9269, 25.421)
  line L109 (-23.0314, 26.0133) -> (-23.2853, 26.1304)
  line L110 (-23.5793, 23.0168) -> (-23.59, 23.012)
  line L111 (-22.7805, 25.8913) -> (-23.0314, 26.0133)
  line L112 (-19.4878, 27.3357) -> (-19.6675, 27.4664)
  line L113 (-21.3955, 25.092) -> (-21.434, 25.1059)
  line L114 (-19.3202, 27.2084) -> (-19.4878, 27.3357)
  line L115 (-21.481, 25.1327) -> (-21.7483, 25.3097)
  line L116 (-21.05, 25.3496) -> (-21.2484, 25.1836)
  line L117 (-23.5801, 24.8259) -> (-23.4823, 24.5959)
  line L118 (-19.0704, 27.0075) -> (-19.3202, 27.2084)
  line L119 (-21.2645, 27.1501) -> (-21.1889, 26.8957)
  line L120 (-24.3795, 23.3849) -> (-24.5959, 23.4823)
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extrude "Extrude3" add sketch "Wheel Gear" along normal blind 2
sketch "Sketch2" plane through (0, 5.5, 0) normal (0, 1, 0) x axis (-1, 0, 0)
  line L1 (34.3261, -23.169) -> (34.3037, -23.1657)
  line L2 (35.1857, -22.2381) -> (35.0772, -22.337)
  line L3 (35.6106, -21.9132) -> (35.4524, -22.0246)
  line L4 (35.7873, -21.7996) -> (35.6106, -21.9132)
  line L5 (36.0309, -24.0107) -> (36.0415, -23.9713)
  line L6 (36.4475, -22.986) -> (36.4792, -22.8267)
  line L7 (34.9829, -22.4304) -> (34.9043, -22.5151)
  line L8 (34.7175, -22.7586) -> (34.6355, -22.9069)
  line L9 (34.288, -23.1603) -> (34.1406, -23.0975)
  line L10 (34.7871, -22.6579) -> (34.7175, -22.7586)
  line L11 (35.3103, -22.1338) -> (35.1857, -22.2381)
  line L12 (34.3753, -23.1625) -> (34.35, -23.168)
  line L13 (34.3037, -23.1657) -> (34.288, -23.1603)
  line L14 (33.9559, -23.0234) -> (33.7696, -22.9537)
  line L15 (36.1952, -24.3154) -> (36.0693, -24.2162)
  line L16 (34.4018, -23.1526) -> (34.3753, -23.1625)
  line L17 (36.3488, -24.4418) -> (36.1952, -24.3154)
  line L18 (35.9576, -21.6994) -> (35.7873, -21.7996)
  line L19 (34.4293, -23.1381) -> (34.4018, -23.1526)
  line L20 (36.0693, -24.2162) -> (36.0571, -24.205)
  line L21 (36.6184, -24.6791) -> (36.4994, -24.5718)
  line L22 (36.0415, -23.9713) -> (36.0749, -23.8849)
  line L23 (36.2705, -23.5372) -> (36.304, -23.4593)
  line L24 (36.5068, -22.6496) -> (36.5285, -22.4573)
  line L25 (36.0328, -24.1655) -> (36.0255, -24.1407)
  line L26 (36.0434, -24.187) -> (36.0328, -24.1655)
  line L27 (34.35, -23.168) -> (34.3261, -23.169)
  line L28 (34.576, -22.9964) -> (34.5162, -23.0671)
  line L29 (34.9043, -22.5151) -> (34.8394, -22.5912)
  line L30 (36.5434, -22.2478) -> (36.5495, -22.0504)
  line L31 (35.0772, -22.337) -> (34.9829, -22.4304)
  line L32 (36.024, -24.0476) -> (36.0309, -24.0107)
  line L33 (38.6719, -23.8395) -> (38.4783, -23.8789)
  line L34 (36.2156, -23.6466) -> (36.2705, -23.5372)
  line L35 (36.4994, -24.5718) -> (36.3488, -24.4418)
  line L36 (36.3761, -23.2563) -> (36.4128, -23.1287)
  line L37 (36.8274, -24.6823) -> (36.7923, -24.6952)
  line L38 (36.4128, -23.1287) -> (36.4475, -22.986)
  line L39 (36.7003, -24.7095) -> (36.6746, -24.7065)
  line L40 (36.0571, -24.205) -> (36.0434, -24.187)
  line L41 (36.7593, -24.704) -> (36.7285, -24.7088)
  line L42 (36.8645, -24.6651) -> (36.8274, -24.6823)
  line L43 (36.7923, -24.6952) -> (36.7593, -24.704)
  line L44 (36.6746, -24.7065) -> (36.6516, -24.6997)
  line L45 (37.6322, -24.1566) -> (37.5126, -24.2144)
  line L46 (38.0885, -23.983) -> (37.9186, -24.0402)
  line L47 (38.4921, -25.5396) -> (38.5622, -25.4479)
  line L48 (37.9723, -26.082) -> (37.9907, -26.0494)
  line L49 (36.3396, -23.3658) -> (36.3761, -23.2563)
  line L50 (36.0215, -24.1127) -> (36.021, -24.0816)
  line L51 (36.021, -24.0816) -> (36.024, -24.0476)
  line L52 (36.304, -23.4593) -> (36.3396, -23.3658)
  line L53 (36.6315, -24.6893) -> (36.6184, -24.6791)
  line L54 (36.1249, -23.7897) -> (36.2156, -23.6466)
  line L55 (36.7285, -24.7088) -> (36.7003, -24.7095)
  line L56 (36.0749, -23.8849) -> (36.1249, -23.7897)
  line L57 (36.0255, -24.1407) -> (36.0215, -24.1127)
  line L58 (38.4281, -25.6165) -> (38.4921, -25.5396)
  line L59 (38.8828, -24.9165) -> (38.9658, -24.7417)
  line L60 (36.6516, -24.6997) -> (36.6315, -24.6893)
  line L61 (37.9583, -26.1132) -> (37.9723, -26.082)
  line L62 (38.5622, -25.4479) -> (38.6384, -25.3391)
  line L63 (38.7174, -25.2155) -> (38.7992, -25.075)
  line L64 (38.2837, -25.765) -> (38.3711, -25.6793)
  line L65 (36.944, -24.6176) -> (36.8645, -24.6651)
  line L66 (37.155, -24.4386) -> (37.0294, -24.5522)
  line L67 (37.5126, -24.2144) -> (37.4108, -24.2689)
  line L68 (37.2536, -24.366) -> (37.155, -24.4386)
  line L69 (38.2743, -23.929) -> (38.0885, -23.983)
  line L70 (38.0732, -25.9446) -> (38.1514, -25.8709)
  line L71 (38.1514, -26.5603) -> (38.0472, -26.3909)
  line L72 (38.9658, -24.7417) -> (39.0479, -24.5484)
  line L73 (38.3294, -26.8723) -> (38.2517, -26.7322)
  line L74 (37.9186, -24.0402) -> (37.7669, -24.0984)
  line L75 (39.0479, -24.5484) -> (39.1178, -24.3636)
  line L76 (38.3711, -25.6793) -> (38.4281, -25.6165)
  line L77 (38.7992, -25.075) -> (38.8828, -24.9165)
  line L78 (38.6384, -25.3391) -> (38.7174, -25.2155)
  line L79 (38.1514, -25.8709) -> (38.2837, -25.765)
  line L80 (37.4108, -24.2689) -> (37.3247, -24.3198)
  line L81 (37.9603, -26.2562) -> (37.9524, -26.2416)
  line L82 (37.0294, -24.5522) -> (36.944, -24.6176)
  line L83 (38.5261, -26.9432) -> (38.4886, -26.944)
  line L84 (37.9423, -26.1964) -> (37.9434, -26.1705)
  line L85 (39.1141, -26.7618) -> (39.0318, -26.7824)
  line L86 (39.4579, -26.7073) -> (39.3261, -26.7231)
  line L87 (38.5668, -26.9389) -> (38.5261, -26.9432)
  line L88 (37.9454, -26.2201) -> (37.9423, -26.1964)
  line L89 (37.3247, -24.3198) -> (37.2536, -24.366)
  line L90 (37.7669, -24.0984) -> (37.6322, -24.1566)
  line L91 (38.0136, -26.0155) -> (38.0732, -25.9446)
  line L92 (38.4783, -23.8789) -> (38.2743, -23.929)
  line L93 (37.9907, -26.0494) -> (38.0136, -26.0155)
  line L94 (38.0472, -26.3909) -> (37.9603, -26.2562)
  line L95 (40.1406, -28.0611) -> (40.2635, -27.9549)
  line L96 (39.0889, -28.7372) -> (39.0984, -28.7131)
  line L97 (39.2121, -26.7417) -> (39.1141, -26.7618)
  line L98 (39.0318, -26.7824) -> (38.9151, -26.8191)
  line L99 (37.9434, -26.1705) -> (37.9487, -26.1427)
  line L100 (37.9524, -26.2416) -> (37.9454, -26.2201)
  line L101 (38.3736, -26.9164) -> (38.3541, -26.9025)
  line L102 (39.6042, -26.6959) -> (39.4579, -26.7073)
  line L103 (40.1391, -26.7005) -> (39.9459, -26.6912)
  line L104 (38.6573, -26.9199) -> (38.5668, -26.9389)
  line L105 (39.3261, -26.7231) -> (39.2121, -26.7417)
  line L106 (38.7593, -26.8857) -> (38.6573, -26.9199)
  line L107 (38.4546, -26.9416) -> (38.4239, -26.9361)
  line L108 (40.5442, -26.7449) -> (40.3483, -26.7194)
  line L109 (39.1544, -28.6388) -> (39.1824, -28.6139)
  line L110 (39.2944, -28.5416) -> (39.3924, -28.4972)
  line L111 (39.7666, -26.6901) -> (39.6042, -26.6959)
  line L112 (39.0838, -28.7833) -> (39.0841, -28.7607)
  line L113 (38.9151, -26.8191) -> (38.7593, -26.8857)
  line L114 (38.3385, -26.8862) -> (38.3294, -26.8723)
  line L115 (39.2631, -29.5583) -> (39.2491, -29.5388)
  line L116 (38.3541, -26.9025) -> (38.3385, -26.8862)
  line L117 (39.9459, -26.6912) -> (39.7666, -26.6901)
  line L118 (40.2635, -27.9549) -> (40.394, -27.8321)
  line L119 (39.1824, -28.6139) -> (39.2151, -28.5893)
  line L120 (40.6697, -27.5375) -> (40.7958, -27.3855)
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extrude "Extrude1" new body sketch "Sketch2" along normal blind 2
work_plane "WorkPlane1" AlongDistance 0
